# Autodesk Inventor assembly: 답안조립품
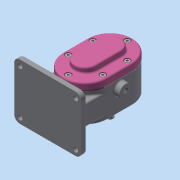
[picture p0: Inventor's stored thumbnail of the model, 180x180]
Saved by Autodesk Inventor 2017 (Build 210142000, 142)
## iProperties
Part Number: 답안조립품
Material: 일반
Document SubType Name: Assembly
Designer: 7-1
Author: 7-1
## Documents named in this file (11)
- C:\Users\7-1\Desktop\700906V1010\답안조립품.iam
- C:\Users\7-1\Desktop\700906V1010\본체.ipt
- C:\Users\7-1\Desktop\700906V1010\베어링부시.ipt
- C:\Users\7-1\Desktop\700906V1010\스퍼기어.ipt
- C:\Users\7-1\Desktop\700906V1010\메인축.ipt
- C:\Users\7-1\Desktop\700906V1010\키 6 x 6 x 18.ipt
- C:\Users\7-1\Desktop\700906V1010\서브축.ipt
- C:\Users\7-1\Desktop\700906V1010\오일 실 16 28 7.ipt
- C:\Users\7-1\Desktop\700906V1010\개스킷.ipt
- C:\Users\7-1\Desktop\700906V1010\커버.ipt
- C:\Users\7-1\Desktop\700906V1010\볼트 M5.ipt
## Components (1 placed, 1 different names)
1. 개스킷:1
